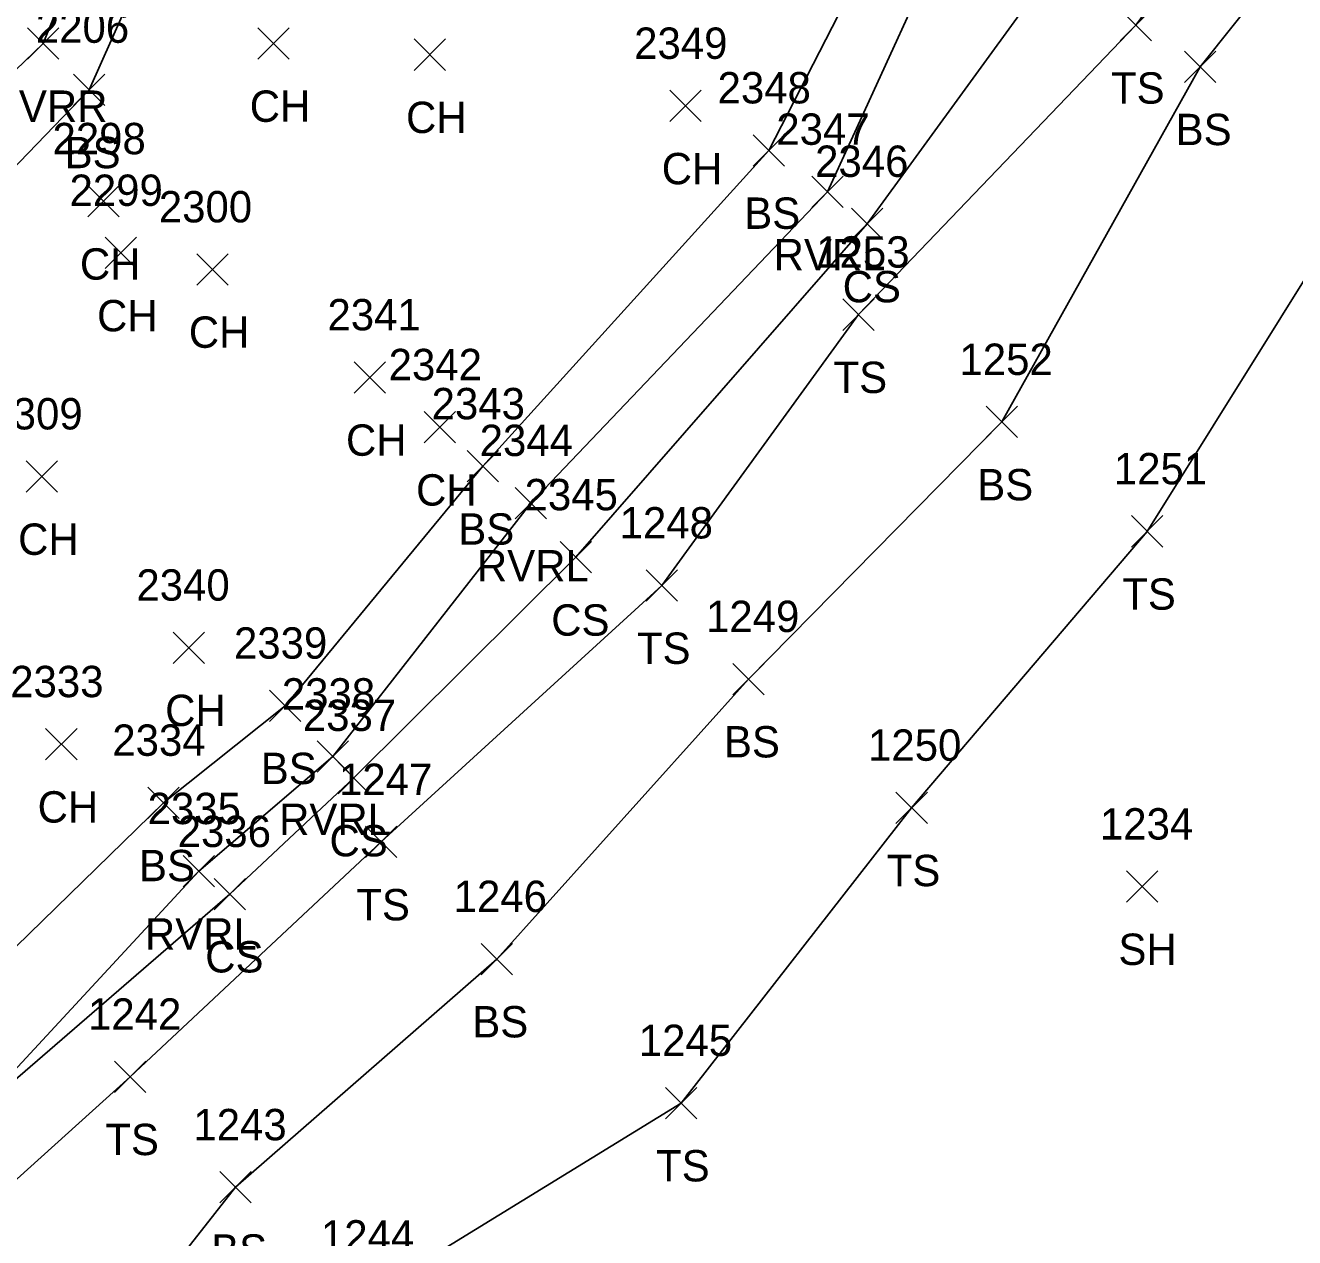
# Model space of a CAD drawing. Extents: x 1459992 to 1461532, y 647785 to 648535.
# Drawn here: x 1461256.6 to 1461337.5, y 648040.8 to 648118.2 of the extents above; entities that cross this region are included whole.
import ezdxf

# ---------------------------------------------------------------- set-up
doc = ezdxf.new("R2010")
doc.units = 0
for name, color, linetype in [('L_A', 7, 'Continuous'), ('L_I', 7, 'Continuous'), ('L_TIC', 7, 'Continuous'), ('LAWE', 7, 'Continuous'), ('LELB', 7, 'Continuous')]:
    doc.layers.add(name, color=color, linetype=linetype)

msp = doc.modelspace()

# ---------------------------------------------------------------- linework, layer by layer
at = {"layer": 'L_TIC'}
for points in [[(1461326.419, 648117.176), (1461328.419, 648119.176)], [(1461328.419, 648117.176), (1461326.419, 648119.176)], [(1461256.751, 648116.016), (1461258.751, 648118.016)], [(1461258.751, 648116.016), (1461256.751, 648118.016)], [(1461271.425, 648116.017), (1461273.425, 648118.017)], [(1461273.425, 648116.017), (1461271.425, 648118.017)], [(1461281.39, 648115.302), (1461283.39, 648117.302)], [(1461283.39, 648115.302), (1461281.39, 648117.302)], [(1461330.511, 648114.53), (1461332.511, 648116.53)], [(1461332.511, 648114.53), (1461330.511, 648116.53)], [(1461259.669, 648113.058), (1461261.669, 648115.058)], [(1461261.669, 648113.058), (1461259.669, 648115.058)], [(1461297.693, 648112.034), (1461299.693, 648114.034)], [(1461299.693, 648112.034), (1461297.693, 648114.034)], [(1461303.003, 648109.191), (1461305.003, 648111.191)], [(1461305.003, 648109.191), (1461303.003, 648111.191)], [(1461260.597, 648105.95), (1461262.597, 648107.95)], [(1461262.597, 648105.95), (1461260.597, 648107.95)], [(1461306.75, 648106.551), (1461308.75, 648108.551)], [(1461308.75, 648106.551), (1461306.75, 648108.551)], [(1461309.278, 648104.504), (1461311.278, 648106.504)], [(1461311.278, 648104.504), (1461309.278, 648106.504)], [(1461261.691, 648102.652), (1461263.691, 648104.652)], [(1461263.691, 648102.652), (1461261.691, 648104.652)], [(1461267.541, 648101.602), (1461269.541, 648103.602)], [(1461269.541, 648101.602), (1461267.541, 648103.602)], [(1461308.728, 648098.716), (1461310.728, 648100.716)], [(1461310.728, 648098.716), (1461308.728, 648100.716)], [(1461277.562, 648094.715), (1461279.562, 648096.715)], [(1461279.562, 648094.715), (1461277.562, 648096.715)], [(1461282.03, 648091.535), (1461284.03, 648093.535)], [(1461284.03, 648091.535), (1461282.03, 648093.535)], [(1461317.859, 648091.871), (1461319.859, 648093.871)], [(1461319.859, 648091.871), (1461317.859, 648093.871)], [(1461284.769, 648089.042), (1461286.769, 648091.042)], [(1461286.769, 648089.042), (1461284.769, 648091.042)], [(1461256.657, 648088.394), (1461258.657, 648090.394)], [(1461258.657, 648088.394), (1461256.657, 648090.394)], [(1461287.833, 648086.698), (1461289.833, 648088.698)], [(1461289.833, 648086.698), (1461287.833, 648088.698)], [(1461327.135, 648084.894), (1461329.135, 648086.894)], [(1461329.135, 648084.894), (1461327.135, 648086.894)], [(1461290.696, 648083.237), (1461292.696, 648085.237)], [(1461292.696, 648083.237), (1461290.696, 648085.237)], [(1461296.191, 648081.439), (1461298.191, 648083.439)], [(1461298.191, 648081.439), (1461296.191, 648083.439)], [(1461266.033, 648077.472), (1461268.033, 648079.472)], [(1461268.033, 648077.472), (1461266.033, 648079.472)], [(1461301.708, 648075.47), (1461303.708, 648077.47)], [(1461303.708, 648075.47), (1461301.708, 648077.47)], [(1461272.176, 648073.771), (1461274.176, 648075.771)], [(1461274.176, 648073.771), (1461272.176, 648075.771)], [(1461257.9, 648071.314), (1461259.9, 648073.314)], [(1461259.9, 648071.314), (1461257.9, 648073.314)], [(1461275.22, 648070.524), (1461277.22, 648072.524)], [(1461277.22, 648070.524), (1461275.22, 648072.524)], [(1461276.559, 648069.159), (1461278.559, 648071.159)], [(1461278.559, 648069.159), (1461276.559, 648071.159)], [(1461264.41, 648067.573), (1461266.41, 648069.573)], [(1461266.41, 648067.573), (1461264.41, 648069.573)], [(1461312.118, 648067.258), (1461314.118, 648069.258)], [(1461314.118, 648067.258), (1461312.118, 648069.258)], [(1461278.296, 648065.077), (1461280.296, 648067.077)], [(1461280.296, 648065.077), (1461278.296, 648067.077)], [(1461266.663, 648063.216), (1461268.663, 648065.216)], [(1461268.663, 648063.216), (1461266.663, 648065.216)], [(1461326.815, 648062.233), (1461328.815, 648064.233)], [(1461328.815, 648062.233), (1461326.815, 648064.233)], [(1461268.635, 648061.753), (1461270.635, 648063.753)], [(1461270.635, 648061.753), (1461268.635, 648063.753)], [(1461285.662, 648057.61), (1461287.662, 648059.61)], [(1461287.662, 648057.61), (1461285.662, 648059.61)], [(1461262.294, 648050.101), (1461264.294, 648052.101)], [(1461264.294, 648050.101), (1461262.294, 648052.101)], [(1461297.413, 648048.424), (1461299.413, 648050.424)], [(1461299.413, 648048.424), (1461297.413, 648050.424)], [(1461269.014, 648043.048), (1461271.014, 648045.048)], [(1461271.014, 648043.048), (1461269.014, 648045.048)]]:
    msp.add_lwpolyline(points, dxfattribs=at)
at = {"layer": 'LAWE'}
for points in [[(1461220.159, 648021.615), (1461235.47, 648039.294), (1461252.966, 648048.327), (1461267.663, 648064.216), (1461276.22, 648071.524), (1461288.833, 648087.698), (1461307.75, 648107.551), (1461316.994, 648127.784), (1461326.453, 648138.792), (1461334.868, 648155.88), (1461340.573, 648163.303), (1461349.799, 648178.335), (1461354.706, 648199.541), (1461353.8, 648220.98), (1461352.341, 648246.452), (1461354.078, 648262.219), (1461358.254, 648276.136), (1461371.394, 648295.376), (1461381.983, 648319.016), (1461394.178, 648330.617), (1461418.251, 648335.818), (1461440.86, 648338.789), (1461464.612, 648337.5), (1461486.388, 648342.471)], [(1461175.582, 648047.692), (1461190.072, 648060.795), (1461210.579, 648076.7), (1461225.386, 648087.992), (1461242.999, 648102.806), (1461257.751, 648117.016), (1461268.272, 648143.142), (1461277.829, 648159.24), (1461282.957, 648175.462), (1461289.558, 648186.996), (1461293.87, 648195.588), (1461292.337, 648203.444)]]:
    msp.add_lwpolyline(points, dxfattribs=at)
at = {"layer": 'LELB'}
for points in [[(1461216.735, 648025.379), (1461232.531, 648043.682), (1461249.111, 648052.696), (1461265.41, 648068.573), (1461273.176, 648074.771), (1461285.769, 648090.042), (1461304.003, 648110.191), (1461314.102, 648129.874), (1461321.787, 648141.876), (1461329.36, 648157.887), (1461338.075, 648167.022), (1461343.94, 648182.363), (1461347.487, 648202.693), (1461348.844, 648222.98), (1461349.522, 648245.94), (1461349.946, 648262.877), (1461353.497, 648277.365), (1461366.77, 648299.226), (1461380.277, 648319.065), (1461391.623, 648332.953), (1461418.599, 648338.961), (1461441.306, 648340.652), (1461465.695, 648340.733), (1461485.923, 648346.235)], [(1461181.212, 648043.592), (1461191.79, 648059.054), (1461212.855, 648073.874), (1461227.371, 648085.596), (1461246.178, 648099.024), (1461260.669, 648114.058), (1461272.144, 648139.82), (1461281.565, 648158.473), (1461288.148, 648173.487), (1461292.193, 648183.75), (1461298.563, 648193.295), (1461300.86, 648204.122), (1461298.63, 648210.737)], [(1461254.788, 648024.689), (1461270.014, 648044.048), (1461286.662, 648058.61), (1461302.708, 648076.47), (1461318.859, 648092.871), (1461331.511, 648115.53), (1461340.274, 648126.529), (1461345.016, 648130.302), (1461347.542, 648139.28), (1461343.673, 648143.434), (1461340.693, 648153.022)], [(1461222.105, 648019.642), (1461239.41, 648035.454), (1461252.966, 648048.327), (1461269.635, 648062.753), (1461277.559, 648070.159), (1461291.696, 648084.237), (1461310.278, 648105.504), (1461323.636, 648123.883), (1461332.795, 648141.481), (1461336.745, 648150.816)], [(1461226.023, 648017.252), (1461244.712, 648034.329), (1461263.294, 648051.101), (1461279.296, 648066.077), (1461297.191, 648082.439), (1461309.728, 648099.716), (1461327.419, 648118.176), (1461335.223, 648128.809), (1461339.468, 648139.304)], [(1461244.522, 647997.797), (1461264.749, 648013.285), (1461278.143, 648036.95), (1461298.413, 648049.424), (1461313.118, 648068.258), (1461328.135, 648085.894), (1461340.87, 648106.284), (1461352.192, 648115.964), (1461353.792, 648121.433), (1461352.841, 648127.816), (1461347.209, 648120.383), (1461340.274, 648126.529)]]:
    msp.add_lwpolyline(points, dxfattribs=at)

# ---------------------------------------------------------------- texts
at = {"layer": 'L_A'}
for s, p in [('TS', (1461325.828, 648113.176)), ('RVRR', (1461254.263, 648112.016)), ('CH', (1461270.913, 648112.017)), ('CH', (1461280.879, 648111.302)), ('BS', (1461329.952, 648110.53)), ('BS', (1461259.11, 648109.058)), ('CH', (1461297.181, 648108.034)), ('BS', (1461302.444, 648105.191)), ('CH', (1461260.085, 648101.95)), ('RVRL', (1461304.317, 648102.551)), ('CS', (1461308.719, 648100.504)), ('CH', (1461261.179, 648098.652)), ('CH', (1461267.029, 648097.602)), ('TS', (1461308.137, 648094.716)), ('CH', (1461277.05, 648090.715)), ('CH', (1461281.518, 648087.535)), ('BS', (1461317.3, 648087.871)), ('BS', (1461284.21, 648085.042)), ('CH', (1461256.145, 648084.394)), ('RVRL', (1461285.4, 648082.698)), ('TS', (1461326.544, 648080.894)), ('CS', (1461290.137, 648079.237)), ('TS', (1461295.601, 648077.439)), ('CH', (1461265.521, 648073.472)), ('BS', (1461301.149, 648071.47)), ('BS', (1461271.617, 648069.771)), ('CH', (1461257.389, 648067.314)), ('RVRL', (1461272.787, 648066.524)), ('CS', (1461276, 648065.159)), ('BS', (1461263.851, 648063.573)), ('TS', (1461311.527, 648063.258)), ('TS', (1461277.706, 648061.077)), ('RVRL', (1461264.23, 648059.216)), ('SH', (1461326.303, 648058.233)), ('CS', (1461268.076, 648057.753)), ('BS', (1461285.103, 648053.61)), ('TS', (1461261.704, 648046.101)), ('TS', (1461296.822, 648044.424)), ('BS', (1461268.455, 648039.048))]:
    msp.add_text(s, height=2, dxfattribs=at).set_placement(p)
at = {"layer": 'L_I'}
for s, p in [('2206', (1461257.275, 648117.058)), ('2349', (1461295.425, 648116.034)), ('2348', (1461300.743, 648113.191)), ('2298', (1461258.337, 648109.95)), ('2347', (1461304.49, 648110.551)), ('2346', (1461306.963, 648108.504)), ('2299', (1461259.423, 648106.652)), ('2300', (1461265.116, 648105.602)), ('1253', (1461307.035, 648102.716)), ('2341', (1461275.869, 648098.715)), ('2342', (1461279.77, 648095.535)), ('1252', (1461316.166, 648095.871)), ('2343', (1461282.509, 648093.042)), ('2309', (1461254.31, 648092.394)), ('2344', (1461285.573, 648090.698)), ('1251', (1461326.009, 648088.894)), ('2345', (1461288.436, 648087.237)), ('1248', (1461294.498, 648085.439)), ('2340', (1461263.687, 648081.472)), ('1249', (1461300.007, 648079.47)), ('2339', (1461269.908, 648077.771)), ('2333', (1461255.641, 648075.314)), ('2338', (1461272.96, 648074.524)), ('2337', (1461274.299, 648073.159)), ('2334', (1461262.15, 648071.573)), ('1250', (1461310.338, 648071.258)), ('1247', (1461276.604, 648069.077)), ('2335', (1461264.403, 648067.216)), ('1234', (1461325.122, 648066.233)), ('2336', (1461266.32, 648065.753)), ('1246', (1461283.914, 648061.61)), ('1242', (1461260.602, 648054.101)), ('1245', (1461295.72, 648052.424)), ('1243', (1461267.321, 648047.048)), ('1244', (1461275.45, 648039.95))]:
    msp.add_text(s, height=2, dxfattribs=at).set_placement(p)

doc.saveas('drawing.dxf')
